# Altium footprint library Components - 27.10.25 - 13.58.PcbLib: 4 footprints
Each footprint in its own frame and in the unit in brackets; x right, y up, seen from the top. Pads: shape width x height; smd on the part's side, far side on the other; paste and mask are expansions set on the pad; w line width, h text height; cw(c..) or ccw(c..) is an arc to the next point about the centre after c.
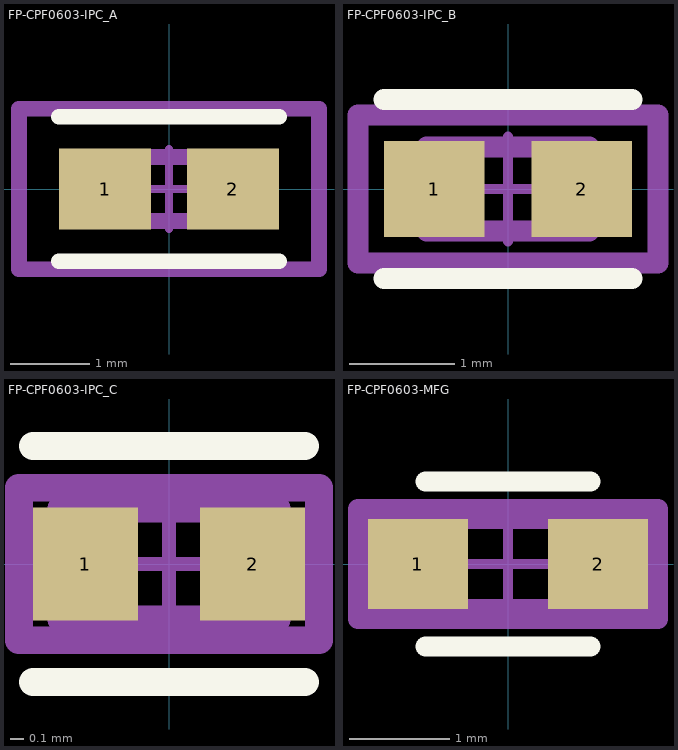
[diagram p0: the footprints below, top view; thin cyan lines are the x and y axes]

## FP-CPF0603-IPC_A [mm]
pads (2):
  rect 1.158x1.012 smd paste+0 mask+0: 1(-0.802,0) 2(0.802,0)
Top Overlay:
  lines w0.2: -1.381,-0.906 1.381,-0.906 ; -1.381,0.906 1.381,0.906
Top Assembly:
  lines w0.2: -1.881,-1.006 1.881,-1.006 1.881,1.006 -1.881,1.006 -1.881,-1.006
  text ".Designator" at 0,0.188 h1
Top 3D Body:
  lines w0.2: -0.775,-0.4 0.775,-0.4 0.775,0.4 -0.775,0.4 -0.775,-0.4
Top Courtyard:
  lines w0.2: -1.881,-1.006 1.881,-1.006 1.881,1.006 -1.881,1.006 -1.881,-1.006
Top Component Center:
  lines w0.1: -0.5,0 0.5,0 ; 0,-0.5 0,0.5
3D body "Res_TE_Connectivity_CPF0603B2K55E1_eec.STEP": height 0.25, standoff 0, extent -1.881,-1.006 1.881,1.006

## FP-CPF0603-IPC_B [mm]
pads (2):
  rect 0.958x0.912 smd paste+0 mask+0: 1(-0.702,0) 2(0.702,0)
Top Overlay:
  lines w0.2: -1.181,-0.856 1.181,-0.856 ; -1.181,0.856 1.181,0.856
Top Assembly:
  lines w0.2: -1.431,-0.706 1.431,-0.706 1.431,0.706 -1.431,0.706 -1.431,-0.706
  text ".Designator" at 0,0.188 h1
Top 3D Body:
  lines w0.2: -0.775,-0.4 0.775,-0.4 0.775,0.4 -0.775,0.4 -0.775,-0.4
Top Courtyard:
  lines w0.2: -1.431,-0.706 1.431,-0.706 1.431,0.706 -1.431,0.706 -1.431,-0.706
Top Component Center:
  lines w0.1: -0.5,0 0.5,0 ; 0,-0.5 0,0.5
3D body "Res_TE_Connectivity_CPF0603B2K55E1_eec.STEP": height 0.25, standoff 0, extent -1.431,-0.706 1.431,0.706

## FP-CPF0603-IPC_C [mm]
pads (2):
  rect 0.758x0.812 smd paste+0 mask+0: 1(-0.602,0) 2(0.602,0)
Top Overlay:
  lines w0.2: -0.981,-0.85 0.981,-0.85 ; -0.981,0.85 0.981,0.85
Top Assembly:
  lines w0.2: -1.081,-0.55 1.081,-0.55 1.081,0.55 -1.081,0.55 -1.081,-0.55
  text ".Designator" at 0,0.188 h1
Top 3D Body:
  lines w0.2: -0.775,-0.4 0.775,-0.4 0.775,0.4 -0.775,0.4 -0.775,-0.4
Top Courtyard:
  lines w0.2: -1.081,-0.55 1.081,-0.55 1.081,0.55 -1.081,0.55 -1.081,-0.55
Top Component Center:
  lines w0.1: -0.5,0 0.5,0 ; 0,-0.5 0,0.5
3D body "Res_TE_Connectivity_CPF0603B2K55E1_eec.STEP": height 0.25, standoff 0, extent -1.081,-0.55 1.081,0.55

## FP-CPF0603-MFG [mm]
pads (2):
  rect 1x0.9 smd paste+0 mask+0: 1(-0.9,0) 2(0.9,0)
Top Overlay:
  lines w0.2: -0.825,-0.825 0.825,-0.825 ; -0.825,0.825 0.825,0.825
Top Assembly:
  lines w0.2: -1.5,-0.55 1.5,-0.55 1.5,0.55 -1.5,0.55 -1.5,-0.55
  text ".Designator" at 0,0.188 h1
Top 3D Body:
  lines w0.2: -0.825,-0.45 0.825,-0.45 0.825,0.45 -0.825,0.45 -0.825,-0.45
Top Courtyard:
  lines w0.2: -1.5,-0.55 1.5,-0.55 1.5,0.55 -1.5,0.55 -1.5,-0.55
Top Component Center:
  lines w0.1: -0.5,0 0.5,0 ; 0,-0.5 0,0.5
3D body "Res_TE_Connectivity_CPF0603B2K55E1_eec.STEP": height 0.25, standoff 0, extent -1.5,-0.55 1.5,0.55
